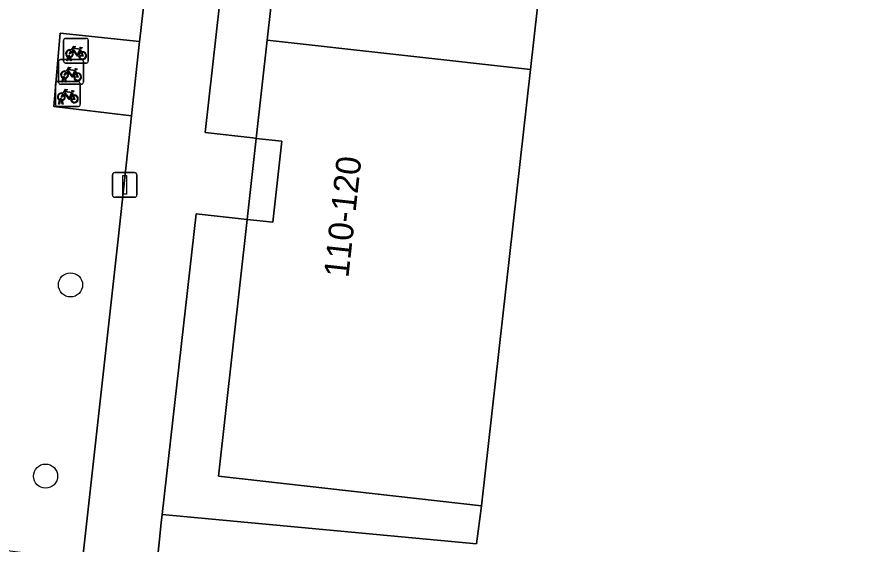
# Model space of a CAD drawing. Extents: x 161928 to 163071, y 386474 to 387428.
# Drawn here: x 162257.83 to 162291.77, y 386676.12 to 386697.44 of the extents above; entities that cross this region are included whole.
import ezdxf

# ---------------------------------------------------------------- set-up
doc = ezdxf.new("R2010")
doc.units = 0
for name, color, linetype in [('IMGEO_Boom', 7, 'Continuous'), ('IMGEO_Fietsenrek', 7, 'Continuous'), ('IMGEO_Grasland_overig', 7, 'Continuous'), ('IMGEO_Groenvoorziening', 7, 'Continuous'), ('IMGEO_Lichtmast', 7, 'Continuous'), ('IMGEO_Pand', 7, 'Continuous'), ('IMGEO_Pand_nummerreeks', 7, 'Continuous'), ('IMGEO_Voetpad_open', 7, 'Continuous')]:
    doc.layers.add(name, color=color, linetype=linetype)

msp = doc.modelspace()

# ---------------------------------------------------------------- linework, layer by layer
at = {"layer": 'IMGEO_Boom'}
for centre in [(162260.002, 386686.602), (162258.994, 386678.87)]:
    msp.add_circle(centre, 0.489, dxfattribs=at)
at = {"layer": 'IMGEO_Fietsenrek'}
for p, q in [((162259.723, 386695.644), (162259.723, 386696.485)), ((162259.723, 386696.485), (162259.723, 386695.644)), ((162259.798, 386696.569), (162260.639, 386696.569)), ((162260.639, 386696.569), (162259.798, 386696.569)), ((162260.723, 386696.494), (162260.723, 386695.653)), ((162260.723, 386695.653), (162260.723, 386696.494)), ((162260.41, 386696.118), (162260.446, 386696.023)), ((162259.522, 386694.787), (162259.522, 386695.628)), ((162259.522, 386695.628), (162259.522, 386694.787)), ((162259.597, 386695.712), (162260.438, 386695.712)), ((162260.438, 386695.712), (162259.597, 386695.712)), ((162259.85, 386695.653), (162259.889, 386695.813)), ((162259.884, 386695.653), (162259.85, 386695.653)), ((162259.919, 386695.801), (162259.884, 386695.653)), ((162259.961, 386695.825), (162259.96, 386695.829)), ((162260.002, 386695.653), (162259.968, 386695.795)), ((162259.992, 386695.836), (162259.993, 386695.829)), ((162260, 386695.799), (162260.035, 386695.653)), ((162260.035, 386695.653), (162260.002, 386695.653)), ((162260.522, 386695.637), (162260.522, 386694.796)), ((162260.522, 386694.796), (162260.522, 386695.637)), ((162260.648, 386695.569), (162259.807, 386695.569)), ((162259.807, 386695.569), (162260.648, 386695.569)), ((162260.209, 386695.261), (162260.245, 386695.166)), ((162259.649, 386694.796), (162259.688, 386694.956)), ((162259.718, 386694.944), (162259.683, 386694.796)), ((162259.76, 386694.968), (162259.759, 386694.972)), ((162259.801, 386694.796), (162259.767, 386694.938)), ((162259.791, 386694.979), (162259.792, 386694.972)), ((162259.799, 386694.942), (162259.834, 386694.796)), ((162259.393, 386693.895), (162259.393, 386694.736)), ((162259.393, 386694.736), (162259.393, 386693.895)), ((162259.468, 386694.82), (162260.309, 386694.82)), ((162260.309, 386694.82), (162259.468, 386694.82)), ((162260.447, 386694.712), (162259.606, 386694.712)), ((162259.606, 386694.712), (162260.447, 386694.712)), ((162259.683, 386694.796), (162259.649, 386694.796)), ((162259.834, 386694.796), (162259.801, 386694.796)), ((162260.393, 386694.745), (162260.393, 386693.904)), ((162260.393, 386693.904), (162260.393, 386694.745)), ((162260.08, 386694.369), (162260.116, 386694.274)), ((162259.52, 386693.904), (162259.559, 386694.064)), ((162259.554, 386693.904), (162259.52, 386693.904)), ((162259.589, 386694.052), (162259.554, 386693.904)), ((162259.631, 386694.076), (162259.63, 386694.08)), ((162259.672, 386693.904), (162259.638, 386694.046)), ((162259.662, 386694.087), (162259.663, 386694.08)), ((162259.67, 386694.05), (162259.705, 386693.904)), ((162259.705, 386693.904), (162259.672, 386693.904)), ((162260.318, 386693.82), (162259.477, 386693.82)), ((162259.477, 386693.82), (162260.318, 386693.82))]:
    msp.add_line(p, q, dxfattribs=at)
for points in [[(162260.036, 386696.095), (162260.131, 386696.259), (162260.217, 386696.245), (162260.219, 386696.236), (162260.163, 386696.225), (162260.136, 386696.18), (162260.392, 386696.139)], [(162260.057, 386696.043), (162260.005, 386695.953), (162259.965, 386695.928), (162259.966, 386695.975), (162260.021, 386696.069)], [(162260.332, 386695.851), (162260.282, 386695.851), (162260.091, 386696.102), (162260.072, 386696.07)], [(162260.379, 386696.114), (162260.122, 386696.155), (162260.105, 386696.126), (162260.272, 386695.906), (162260.379, 386696.114)], [(162260.427, 386696.016), (162260.397, 386696.093), (162260.288, 386695.875), (162260.331, 386695.875)], [(162260.361, 386695.875), (162260.481, 386695.874), (162260.437, 386695.988)], [(162260.457, 386695.995), (162260.512, 386695.85), (162260.362, 386695.85)], [(162260.392, 386696.139), (162260.417, 386696.188), (162260.411, 386696.192), (162260.388, 386696.196), (162260.376, 386696.203), (162260.375, 386696.206), (162260.377, 386696.211), (162260.472, 386696.196), (162260.474, 386696.186), (162260.464, 386696.173), (162260.452, 386696.167), (162260.438, 386696.173), (162260.41, 386696.118)], [(162259.835, 386695.238), (162259.93, 386695.402), (162260.016, 386695.388), (162260.018, 386695.379), (162259.962, 386695.368), (162259.935, 386695.323), (162260.191, 386695.282)], [(162260.131, 386694.994), (162260.081, 386694.994), (162259.89, 386695.245), (162259.871, 386695.213)], [(162260.178, 386695.257), (162259.921, 386695.298), (162259.904, 386695.269), (162260.071, 386695.049), (162260.178, 386695.257)], [(162260.226, 386695.159), (162260.196, 386695.236), (162260.087, 386695.018), (162260.13, 386695.018)], [(162260.191, 386695.282), (162260.216, 386695.331), (162260.21, 386695.335), (162260.187, 386695.339), (162260.175, 386695.346), (162260.174, 386695.349), (162260.176, 386695.354), (162260.271, 386695.339), (162260.273, 386695.329), (162260.263, 386695.316), (162260.251, 386695.31), (162260.237, 386695.316), (162260.209, 386695.261)], [(162259.856, 386695.186), (162259.804, 386695.096), (162259.764, 386695.071), (162259.765, 386695.118), (162259.82, 386695.212)], [(162260.16, 386695.018), (162260.28, 386695.017), (162260.236, 386695.131)], [(162260.256, 386695.138), (162260.311, 386694.993), (162260.161, 386694.993)], [(162259.727, 386694.294), (162259.675, 386694.204), (162259.635, 386694.179), (162259.636, 386694.226), (162259.691, 386694.32)], [(162259.706, 386694.346), (162259.801, 386694.51), (162259.887, 386694.496), (162259.889, 386694.487), (162259.833, 386694.476), (162259.806, 386694.431), (162260.062, 386694.39)], [(162260.002, 386694.102), (162259.952, 386694.102), (162259.761, 386694.353), (162259.742, 386694.321)], [(162260.049, 386694.365), (162259.792, 386694.406), (162259.775, 386694.377), (162259.942, 386694.157), (162260.049, 386694.365)], [(162260.097, 386694.267), (162260.067, 386694.344), (162259.958, 386694.126), (162260.001, 386694.126)], [(162260.031, 386694.126), (162260.151, 386694.125), (162260.107, 386694.239)], [(162260.127, 386694.246), (162260.182, 386694.101), (162260.032, 386694.101)], [(162260.062, 386694.39), (162260.087, 386694.439), (162260.081, 386694.443), (162260.058, 386694.447), (162260.046, 386694.454), (162260.045, 386694.457), (162260.047, 386694.462), (162260.142, 386694.447), (162260.144, 386694.437), (162260.134, 386694.424), (162260.122, 386694.418), (162260.108, 386694.424), (162260.08, 386694.369)]]:
    msp.add_lwpolyline(points, dxfattribs=at)
for centre, radius, start, end in [((162259.801, 386696.491), 0.0779, 92.4484, 184.2845), ((162259.801, 386696.491), 0.0779, 92.4484, 184.2845), ((162260.645, 386696.491), 0.0779, 2.4484, 94.2845), ((162260.645, 386696.491), 0.0779, 2.4484, 94.2845), ((162259.963, 386695.954), 0.159, 62.6766, 242.1369), ((162259.963, 386695.954), 0.129, 63.3192, 238.903), ((162259.963, 386695.954), 0.129, 283.6043, 43.4302), ((162259.963, 386695.954), 0.159, 283.5766, 46.6042), ((162260.49, 386695.87), 0.159, 113.3408, 178.3217), ((162260.49, 386695.87), 0.159, 187.0065, 105.7708), ((162260.49, 386695.87), 0.129, 113.923, 177.9556), ((162260.49, 386695.87), 0.129, 188.6715, 104.5883), ((162259.6, 386695.634), 0.0779, 92.4484, 184.2845), ((162259.6, 386695.634), 0.0779, 92.4484, 184.2845), ((162259.801, 386695.647), 0.0779, 182.4484, 274.2845), ((162259.801, 386695.647), 0.0779, 182.4484, 274.2845), ((162259.943, 386695.825), 0.0499, 12.8025, 158.6934), ((162259.963, 386695.954), 0.159, 253.9967, 271.7867), ((162259.943, 386695.825), 0.0174, 12.8025, 163.4502), ((162259.963, 386695.954), 0.129, 253.415, 269.0204), ((162260.444, 386695.634), 0.0779, 2.4484, 94.2845), ((162260.444, 386695.634), 0.0779, 2.4484, 94.2845), ((162260.645, 386695.647), 0.0779, 272.4484, 4.2845), ((162260.645, 386695.647), 0.0779, 272.4484, 4.2845), ((162259.762, 386695.097), 0.159, 62.6766, 242.1369), ((162259.762, 386695.097), 0.129, 63.3192, 238.903), ((162259.742, 386694.968), 0.0499, 12.8025, 158.6934), ((162259.762, 386695.097), 0.159, 253.9967, 271.7867), ((162259.742, 386694.968), 0.0174, 12.8025, 163.4502), ((162259.762, 386695.097), 0.129, 253.415, 269.0204), ((162259.762, 386695.097), 0.129, 283.6043, 43.4302), ((162259.762, 386695.097), 0.159, 283.5766, 46.6042), ((162260.289, 386695.013), 0.159, 113.3408, 178.3217), ((162260.289, 386695.013), 0.159, 187.0065, 105.7708), ((162260.289, 386695.013), 0.129, 113.923, 177.9556), ((162260.289, 386695.013), 0.129, 188.6715, 104.5883), ((162259.471, 386694.742), 0.0779, 92.4484, 184.2845), ((162259.471, 386694.742), 0.0779, 92.4484, 184.2845), ((162259.6, 386694.79), 0.0779, 182.4484, 274.2845), ((162259.6, 386694.79), 0.0779, 182.4484, 274.2845), ((162260.315, 386694.742), 0.0779, 2.4484, 94.2845), ((162260.315, 386694.742), 0.0779, 2.4484, 94.2845), ((162260.444, 386694.79), 0.0779, 272.4484, 4.2845), ((162260.444, 386694.79), 0.0779, 272.4484, 4.2845), ((162259.633, 386694.205), 0.159, 62.6766, 242.1369), ((162259.633, 386694.205), 0.129, 63.3192, 238.903), ((162259.633, 386694.205), 0.129, 283.6043, 43.4302), ((162259.633, 386694.205), 0.159, 283.5766, 46.6042), ((162260.16, 386694.121), 0.159, 113.3408, 178.3217), ((162260.16, 386694.121), 0.159, 187.0065, 105.7708), ((162260.16, 386694.121), 0.129, 113.923, 177.9556), ((162260.16, 386694.121), 0.129, 188.6715, 104.5883), ((162259.471, 386693.898), 0.0779, 182.4484, 274.2845), ((162259.471, 386693.898), 0.0779, 182.4484, 274.2845), ((162259.613, 386694.076), 0.0499, 12.8025, 158.6934), ((162259.633, 386694.205), 0.159, 253.9967, 271.7867), ((162259.613, 386694.076), 0.0174, 12.8025, 163.4502), ((162259.633, 386694.205), 0.129, 253.415, 269.0204), ((162260.315, 386693.898), 0.0779, 272.4484, 4.2845), ((162260.315, 386693.898), 0.0779, 272.4484, 4.2845)]:
    msp.add_arc(centre, radius, start, end, dxfattribs=at)
at = {"layer": 'IMGEO_Grasland_overig'}
for points in [[(162268.251, 386700.492), (162266.341, 386700.702), (162265.448, 386692.762), (162267.38, 386692.54), (162267.51, 386692.526), (162267.955, 386696.501), (162268.4, 386700.476)], [(162267.02, 386689.26), (162265.077, 386689.473), (162263.71, 386677.32), (162276.413, 386676.138), (162276.622, 386677.674), (162265.981, 386678.865), (162267.143, 386689.247)]]:
    msp.add_lwpolyline(points, close=True, dxfattribs=at)
at = {"layer": 'IMGEO_Groenvoorziening'}
for points in [[(162309.792, 386729.394), (162283.611, 386732.74), (162283.89, 386734.923), (162272.369, 386736.187), (162271.904, 386732.25), (162269.912, 386732.425), (162269.851, 386731.887), (162271.891, 386731.651), (162282.543, 386730.474), (162282.466, 386729.788), (162280.566, 386712.844), (162278.599, 386695.307), (162276.622, 386677.674), (162276.413, 386676.138), (162263.71, 386677.32), (162263.671, 386676.976), (162263.477, 386675.126), (162265.931, 386674.909), (162298.443, 386671.239)], [(162244.705, 386702.233), (162243.065, 386687.829), (162243.049, 386687.699), (162244.536, 386687.564), (162244.235, 386684.547), (162242.69, 386684.749), (162241.934, 386677.547), (162246.429, 386677.056), (162255.881, 386676.067), (162260.486, 386675.473), (162261.932, 386688.446), (162262.467, 386693.434), (162259.33, 386693.811), (162259.59, 386696.782), (162262.789, 386696.438), (162262.8, 386696.541), (162263.719, 386704.596)]]:
    msp.add_lwpolyline(points, dxfattribs=at)
at = {"layer": 'IMGEO_Lichtmast'}
for p, q in [((162261.699, 386690.245), (162261.699, 386691.045)), ((162261.699, 386691.045), (162261.699, 386690.245)), ((162261.799, 386691.145), (162262.589, 386691.145)), ((162262.589, 386691.145), (162261.799, 386691.145)), ((162262.689, 386691.045), (162262.689, 386690.245)), ((162262.689, 386690.245), (162262.689, 386691.045)), ((162262.589, 386690.145), (162261.799, 386690.145)), ((162261.799, 386690.145), (162262.589, 386690.145))]:
    msp.add_line(p, q, dxfattribs=at)
msp.add_lwpolyline([(162262.119, 386691.02), (162262.269, 386691.02), (162262.269, 386690.27), (162262.119, 386690.27), (162262.119, 386691.02)], dxfattribs=at)
for centre, start, end in [((162261.799, 386691.045), 90, 180), ((162261.799, 386691.045), 90, 180), ((162262.589, 386691.045), 0, 90), ((162262.589, 386691.045), 360, 90), ((162261.799, 386690.245), 180, 270), ((162261.799, 386690.245), 180, 270), ((162262.589, 386690.245), 270, 0), ((162262.589, 386690.245), 270, 0)]:
    msp.add_arc(centre, 0.1, start, end, dxfattribs=at)
at = {"layer": 'IMGEO_Pand'}
for points in [[(162280.566, 386712.844), (162269.917, 386714.021), (162268.767, 386703.756), (162269.775, 386703.646), (162269.416, 386700.365), (162268.4, 386700.476), (162267.955, 386696.501), (162278.599, 386695.307)], [(162267.51, 386692.526), (162268.544, 386692.413), (162268.184, 386689.133), (162267.143, 386689.247), (162265.981, 386678.865), (162276.622, 386677.674), (162278.599, 386695.307), (162267.955, 386696.501)]]:
    msp.add_lwpolyline(points, close=True, dxfattribs=at)
at = {"layer": 'IMGEO_Voetpad_open'}
msp.add_lwpolyline([(162263.719, 386704.596), (162262.8, 386696.541), (162262.789, 386696.438), (162262.467, 386693.434), (162261.932, 386688.446), (162260.486, 386675.473), (162263.477, 386675.126), (162263.671, 386676.976), (162263.71, 386677.32), (162265.077, 386689.473), (162267.02, 386689.26), (162267.143, 386689.247), (162267.51, 386692.526), (162267.38, 386692.54), (162265.448, 386692.762), (162266.341, 386700.702)], dxfattribs=at)
for points in [[(162262.789, 386696.438), (162259.59, 386696.782), (162259.33, 386693.811), (162262.467, 386693.434)], [(162267.143, 386689.247), (162268.184, 386689.133), (162268.544, 386692.413), (162267.51, 386692.526)]]:
    msp.add_lwpolyline(points, close=True, dxfattribs=at)

# ---------------------------------------------------------------- texts
at = {"layer": 'IMGEO_Pand_nummerreeks'}
msp.add_text('110-120', height=1, rotation=83.7365, dxfattribs=at).set_placement((162271.235, 386686.864))

doc.saveas('drawing.dxf')
